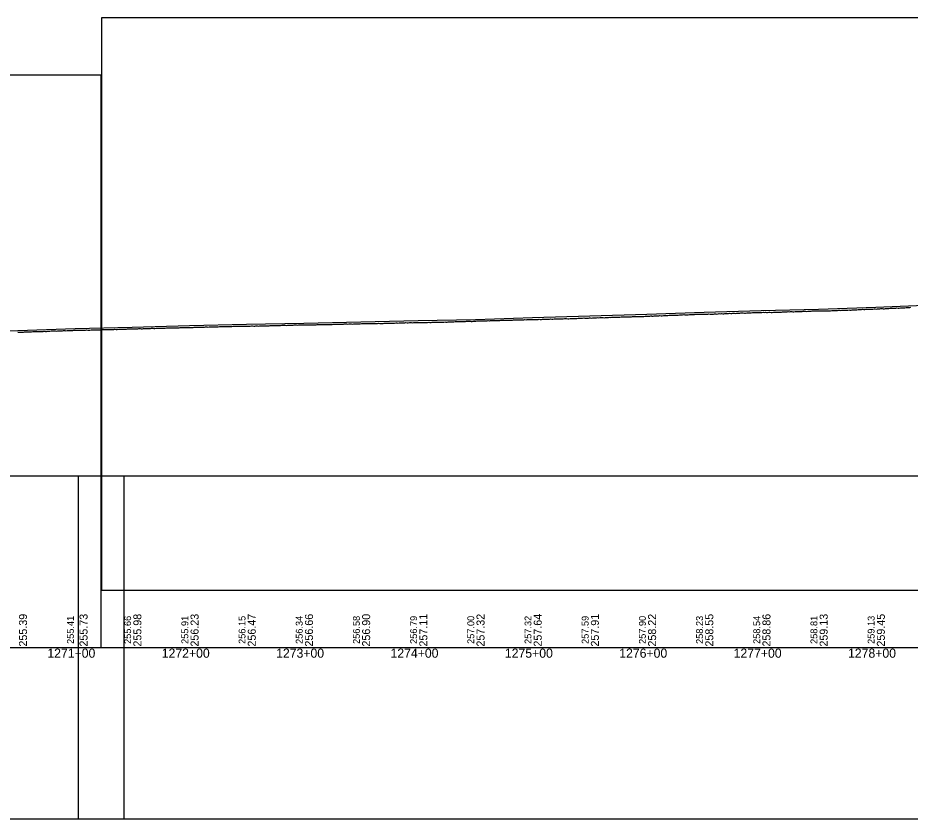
# Model space of a CAD drawing. Extents: x -3627 to 47473, y 2850 to 4350.
# Drawn here: x 14427 to 15207, y 2850 to 3550 of the extents above; entities that cross this region are included whole.
import ezdxf

# ---------------------------------------------------------------- set-up
doc = ezdxf.new("R2010")
doc.units = 0
for name, color, linetype in [('RD_DDB_Profile_EX', 7, 'Continuous'), ('RD_DDB_Profile_PR', 7, 'Continuous'), ('RD_DDB_StaTX', 7, 'Continuous'), ('RD_DDB_StripGrade', 7, 'Continuous'), ('RD_GPK_Profile_Cell', 7, 'Continuous'), ('RD_SHT_ShtClip', 7, 'Continuous')]:
    doc.layers.add(name, color=color, linetype=linetype)

msp = doc.modelspace()

# ---------------------------------------------------------------- linework, layer by layer
at = {"layer": 'RD_DDB_Profile_EX'}
for points in [[(15040.535467, 3291.620115), (15041.532076, 3291.55583), (15042.536778, 3291.601915), (15043.533383, 3291.53178), (15044.532911, 3291.473685), (15045.53718, 3291.79702), (15046.533783, 3291.75525), (15047.055087, 3291.729195), (15047.537993, 3291.70876), (15048.534898, 3291.79854), (15049.533692, 3291.897145), (15050.538461, 3291.854445), (15051.534928, 3291.80897), (15052.539074, 3291.9163), (15053.535543, 3291.881615), (15054.534341, 3291.83489), (15055.531853, 3291.970315), (15056.535996, 3292.016485), (15057.540017, 3292.162725), (15058.531012, 3292.105165), (15059.535031, 3292.190165), (15060.531356, 3292.23045), (15061.536415, 3292.30237), (15062.540443, 3292.116995), (15063.531429, 3292.1353), (15064.535456, 3292.270565), (15065.531766, 3292.289205), (15065.877865, 3292.27198), (15066.535716, 3292.24281), (15067.52716, 3292.239205), (15068.531475, 3292.335665), (15069.53538, 3292.48212), (15070.531541, 3292.5791), (15070.834701, 3292.5323), (15071.832752, 3292.53189), (15072.843867, 3292.481505), (15073.84248, 3292.48485), (15074.841012, 3292.580685), (15075.289254, 3292.625415), (15075.839032, 3292.67243), (15076.842887, 3292.67256), (15077.840872, 3292.714085), (15078.839485, 3292.771515), (15079.83748, 3292.67516), (15080.84131, 3292.80466), (15081.839829, 3292.666525), (15082.8449, 3292.619625), (15083.842884, 3292.86472), (15084.841555, 3292.909615), (15085.845284, 3292.682165), (15086.843214, 3292.731925), (15087.841727, 3292.90888), (15088.839665, 3292.999085), (15089.863008, 3292.926955), (15090.861194, 3292.921985), (15091.866519, 3292.97603), (15092.864692, 3292.88544), (15094.112032, 3292.945095), (15094.866936, 3292.940265), (15095.865008, 3293.045085), (15096.863672, 3293.145045), (15097.861749, 3293.260005), (15098.865197, 3293.18511), (15099.863867, 3293.229995), (15100.86923, 3293.339735), (15101.8673, 3293.25), (15102.865993, 3293.405215), (15103.869383, 3293.394825), (15104.867353, 3293.260425), (15105.865949, 3293.310475), (15106.863923, 3293.4), (15107.86724, 3293.444775), (15108.865837, 3293.54475), (15109.871054, 3293.562415), (15110.869668, 3293.601435), (15111.86764, 3293.472835), (15112.93481, 3293.45523), (15113.869462, 3293.667605), (15114.867335, 3293.66203), (15115.865207, 3293.62275), (15116.869049, 3293.571515), (15117.866922, 3293.721615), (15118.864794, 3293.88258), (15119.870539, 3293.810775), (15120.873732, 3293.754645), (15121.8716, 3294.10549), (15122.346199, 3294.1055), (15122.870076, 3294.1055), (15123.867848, 3294.094485), (15124.86628, 3294.088965), (15125.869366, 3294.044555), (15126.867139, 3294.05), (15127.865564, 3294.05), (15128.870552, 3294.05), (15129.873645, 3294.1), (15130.872073, 3294.1), (15131.869834, 3294.061005), (15132.867508, 3294.11101), (15133.86584, 3294.116495), (15134.868833, 3294.15), (15135.866507, 3294.18374)], [(15135.866507, 3294.18374), (15136.864829, 3294.1), (15137.869722, 3294.194505), (15138.873377, 3294.283795), (15139.871051, 3294.36757), (15140.868726, 3294.36755), (15141.168977, 3294.3525), (15141.866977, 3294.328425), (15142.864554, 3294.33923), (15143.867468, 3294.42883), (15144.865676, 3294.52363), (15145.863253, 3294.53947), (15146.805248, 3294.478535), (15147.809884, 3294.56749), (15148.80952, 3294.57771), (15149.809143, 3294.555725), (15150.814609, 3294.59422), (15151.848124, 3294.64405), (15152.845877, 3294.64405), (15153.846573, 3294.81331), (15154.85195, 3294.731415), (15155.853308, 3294.712695), (15156.858661, 3294.97429), (15157.85934, 3294.917045), (15158.852502, 3294.989895), (15159.991754, 3295.022785), (15160.859106, 3295.058595), (15161.864236, 3295.108165), (15162.864757, 3295.193), (15163.869855, 3295.221215), (15164.863727, 3295.220955), (15165.864274, 3295.385175), (15166.869354, 3295.33503), (15167.869885, 3295.31528), (15168.875757, 3295.415395), (15169.403143, 3295.46827), (15169.876208, 3295.47646), (15170.875115, 3295.526455), (15171.875512, 3295.57603), (15172.875909, 3295.567465), (15173.881623, 3295.559095), (15174.88202, 3295.6167), (15175.886842, 3295.74967), (15176.887224, 3295.707345), (15177.885716, 3295.6), (15178.886111, 3295.70865), (15179.886346, 3295.87366), (15180.890954, 3295.864665), (15181.891175, 3296.028265), (15182.896717, 3295.99598), (15183.889815, 3295.940935), (15184.894396, 3295.95), (15185.894627, 3296.094495), (15186.895853, 3296.1719), (15187.900401, 3296.24058), (15188.225921, 3296.20799), (15188.900517, 3296.140455), (15189.897832, 3296.37385), (15190.897901, 3296.351795), (15191.903276, 3296.36133), (15192.903345, 3296.47937), (15193.903414, 3296.529735), (15194.907732, 3296.449785), (15195.901888, 3296.55999), (15196.906206, 3296.460035), (15197.906237, 3296.47031), (15198.910363, 3296.66019), (15199.911349, 3296.67056), (15200.911256, 3296.76039), (15201.908454, 3296.8), (15202.908369, 3296.820935), (15203.914297, 3296.86052), (15204.915341, 3296.878775), (15205.919426, 3296.928705), (15207.048699, 3297.002285), (15207.912279, 3297.121585)], [(14753.655646, 3283.3), (14754.659692, 3283.34781), (14755.30203, 3283.31564), (14755.655629, 3283.302085), (14756.659588, 3283.2938), (14757.657479, 3283.430715), (14758.653684, 3283.49593), (14759.657325, 3283.402015), (14760.653781, 3283.5481), (14761.657498, 3283.596225), (14762.661166, 3283.546265), (14763.65151, 3283.59445), (14764.713419, 3283.641595), (14765.651576, 3283.60171), (14766.65518, 3283.79664), (14767.658843, 3283.60165), (14768.649038, 3283.601625), (14769.652906, 3283.74522), (14770.648955, 3283.74707), (14771.611445, 3283.75), (14772.609229, 3283.701505), (14773.613071, 3283.75), (14774.124808, 3283.77565), (14774.610385, 3283.79693), (14775.614136, 3283.898505), (14776.604161, 3283.894185), (14777.607723, 3283.945755), (14778.611251, 3283.94863), (14779.608927, 3283.998575), (14780.6125, 3283.998615), (14781.610178, 3283.99856), (14782.613703, 3283.998605), (14783.603525, 3283.951355), (14784.607174, 3283.951305), (14785.610625, 3283.9525), (14786.608027, 3284.1), (14787.611684, 3283.95248), (14788.609246, 3283.95), (14789.612549, 3284.05246), (14790.602411, 3284.1), (14791.607833, 3284.2), (14792.611443, 3284.14892), (14792.947586, 3284.132055), (14793.608982, 3284.1), (14794.612297, 3284.15105), (14795.609663, 3284.19783), (14796.605251, 3284.149075), (14797.602624, 3284.153845), (14798.605952, 3284.299105), (14799.609532, 3284.25), (14800.606906, 3284.348265), (14801.610243, 3284.3), (14802.607584, 3284.25167), (14803.602986, 3284.351985), (14804.600246, 3284.5), (14805.603484, 3284.451215), (14806.606805, 3284.402115), (14807.604151, 3284.45055), (14808.607403, 3284.499525), (14809.596654, 3284.648805), (14810.599921, 3284.7), (14811.770364, 3284.70863), (14812.600439, 3284.749745), (14813.603603, 3284.749835), (14814.600747, 3284.700175), (14815.603945, 3284.75008), (14816.593133, 3284.84995), (14817.597652, 3284.79943), (14818.594652, 3284.799515), (14819.599167, 3284.898855), (14820.631067, 3284.949515), (14821.181753, 3284.97717), (14821.628093, 3284.999525), (14822.325322, 3284.930535), (14822.632199, 3284.89994), (14823.629233, 3284.85), (14824.628181, 3284.80023), (14825.633222, 3284.998695), (14826.630251, 3284.999675), (14827.635301, 3284.999575), (14828.63233, 3285.197895), (14829.637296, 3285.19689), (14830.634321, 3285.196385), (14831.639322, 3285.2012), (14832.630216, 3285.201375), (14833.635041, 3285.20077), (14834.632085, 3285.347725), (14835.636897, 3285.398315), (14836.641683, 3285.39722), (14837.638608, 3285.445435), (14838.643651, 3285.49801), (14839.634587, 3285.44892), (14840.004531, 3285.467295), (14840.639275, 3285.498845), (14841.636093, 3285.54887), (14842.640914, 3285.59639), (14843.637733, 3285.50353), (14844.642507, 3285.553735), (14845.639326, 3285.59878), (14846.63819, 3285.69722), (14847.635006, 3285.6)], [(14847.635006, 3285.6), (14848.639604, 3285.589965), (14849.644157, 3285.785), (14850.641292, 3285.79415), (14851.645768, 3285.79848), (14852.648598, 3285.801485), (14853.653555, 3285.85), (14854.64458, 3285.89679), (14855.649544, 3285.94667), (14856.646105, 3286.04349), (14857.651069, 3286.044935), (14858.827309, 3285.9606), (14859.652469, 3286.003405), (14860.656986, 3286.098255), (14861.648181, 3286.09461), (14862.652688, 3286.092635), (14863.649401, 3286.14641), (14864.653908, 3286.14448), (14865.650319, 3286.14283), (14866.654916, 3286.14078), (14867.651333, 3286.14282), (14868.238698, 3286.14247), (14868.650567, 3286.148065), (14869.646828, 3286.2), (14870.651484, 3286.38281), (14871.655814, 3286.3364), (14872.652401, 3286.396225), (14873.656735, 3286.444245), (14874.653318, 3286.49255), (14875.657656, 3286.598105), (14876.648739, 3286.598065), (14877.653069, 3286.6), (14878.101109, 3286.6), (14879.099012, 3286.6), (14880.102986, 3286.59797), (14881.100583, 3286.458575), (14882.104858, 3286.504335), (14883.102451, 3286.693155), (14884.099568, 3286.6), (14885.103213, 3286.6), (14886.10114, 3286.75), (14887.105056, 3286.702375), (14888.10296, 3286.79752), (14889.106821, 3286.80498), (14890.097629, 3286.715025), (14891.101487, 3286.844975), (14892.099421, 3286.884305), (14893.103263, 3286.926385), (14894.107497, 3286.831545), (14895.105035, 3286.847265), (14896.108858, 3286.93629), (14896.472864, 3286.973025), (14897.099711, 3287.019755), (14898.103495, 3287.078035), (14899.101415, 3287.08014), (14900.105185, 3287.08017), (14901.103115, 3287.144155), (14902.106483, 3287.085375), (14903.103637, 3287.038645), (14904.10113, 3287.132455), (14905.105325, 3287.223675), (14906.102807, 3287.284965), (14907.106964, 3287.28801), (14908.104415, 3287.15921), (14909.108573, 3287.15612), (14910.099005, 3287.387815), (14911.103161, 3287.337855), (14912.116252, 3287.41981), (14913.114011, 3287.37828), (14914.118137, 3287.384535), (14915.295642, 3287.411725), (14916.112686, 3287.490785), (14917.109899, 3287.584305), (14918.113955, 3287.578175), (14919.111644, 3287.527665), (14920.115699, 3287.577815), (14921.119354, 3287.771615), (14922.117444, 3287.814575), (14923.113831, 3287.771925), (14924.111928, 3287.774505), (14924.707031, 3287.74497), (14925.115549, 3287.731), (14926.113081, 3287.774265), (14927.11666, 3287.964905), (14928.114686, 3287.88377), (14929.111004, 3287.79373), (14930.114989, 3287.809305), (14931.112611, 3288.03102), (14932.116596, 3287.84374), (14933.114217, 3288.01277), (14934.11842, 3288.10314), (14935.115754, 3288.00642), (14936.111913, 3288.09385), (14937.109465, 3288.128115), (14938.113381, 3288.16609), (14939.110933, 3288.0906), (14940.114849, 3288.04382), (14941.118376, 3288.28169), (14942.109027, 3288.15), (14942.754614, 3288.196945), (14943.760798, 3288.3)], [(14943.760798, 3288.3), (14944.763345, 3288.387485), (14945.761478, 3288.290515), (14946.759258, 3288.440395), (14947.757403, 3288.53059), (14948.760475, 3288.493625), (14949.758618, 3288.53068), (14950.764283, 3288.57325), (14951.762442, 3288.619605), (14952.941198, 3288.61451), (14953.762969, 3288.586615), (14954.760595, 3288.683125), (14955.758605, 3288.733015), (14956.769362, 3288.736315), (14957.767374, 3288.786225), (14958.764998, 3288.83264), (14959.763019, 3288.875545), (14960.760646, 3288.92887), (14961.763936, 3288.89309), (14962.352587, 3288.86355), (14962.760917, 3288.843055), (14963.76661, 3288.892865), (14964.764085, 3288.98925), (14965.767242, 3289.035965), (14966.764716, 3289.0859), (14967.762593, 3289.096465), (14968.760069, 3289.08934), (14969.763218, 3289.089565), (14970.76851, 3289.13569), (14971.766391, 3289.13565), (14972.763117, 3289.228475), (14973.723063, 3289.092985), (14974.720315, 3289.082435), (14975.718047, 3289.4219), (14976.722096, 3289.482), (14977.719348, 3289.492785), (14978.723461, 3289.485865), (14979.721196, 3289.482335), (14980.718449, 3289.575225), (14981.175365, 3289.5523), (14981.715696, 3289.532305), (14982.719749, 3289.4259), (14983.723796, 3289.61832), (14984.721038, 3289.72188), (14985.718758, 3289.80795), (14986.722347, 3289.7261), (14987.719588, 3289.59318), (14988.71683, 3289.926165), (14989.721856, 3289.74652), (14990.725447, 3289.75), (14991.722678, 3289.973005), (14992.720367, 3290.01647), (14993.717596, 3289.96996), (14994.721197, 3290.0144), (14995.718428, 3289.974235), (14996.722937, 3290.140155), (14997.720169, 3290.136935), (14998.7174, 3290.273995), (14999.998143, 3290.26415), (15000.71914, 3290.237495), (15001.716358, 3290.1907), (15002.720865, 3290.29055), (15003.724483, 3290.343925), (15004.721705, 3290.34699), (15005.718927, 3290.47014), (15006.716553, 3290.4675), (15007.507182, 3290.473855), (15008.505499, 3290.522575), (15009.510221, 3290.728325), (15010.507741, 3290.58161), (15011.512017, 3290.62823), (15012.50946, 3290.628525), (15013.507726, 3290.52442), (15014.504771, 3290.715225), (15015.50903, 3290.95512), (15016.513693, 3290.874045), (15017.504744, 3290.740125), (15018.508981, 3290.779985), (15018.82092, 3290.87391), (15019.506418, 3291.060555), (15020.510599, 3291.010155), (15021.515286, 3291.00969), (15022.506294, 3291.009245), (15023.510898, 3291.0055), (15024.507892, 3291.11623), (15025.512058, 3291.20908), (15026.503512, 3291.15527), (15027.507672, 3291.15485), (15028.511806, 3291.178985), (15029.532627, 3291.139665), (15030.537045, 3291.28956), (15031.528361, 3291.33593), (15032.533359, 3291.15), (15033.537767, 3291.1), (15034.534503, 3291.14645), (15035.533932, 3291.24268), (15036.530665, 3291.331925), (15037.643698, 3291.514475), (15038.532289, 3291.231985), (15039.536572, 3291.292745), (15040.535467, 3291.620115)], [(14454.367128, 3276.416905), (14455.364059, 3276.41114), (14456.368165, 3276.451255), (14457.359051, 3276.544565), (14458.362235, 3276.523825), (14459.366342, 3276.47045), (14460.363272, 3276.477515), (14461.360888, 3276.436755), (14462.364996, 3276.62674), (14463.361448, 3276.661055), (14464.365555, 3276.61743), (14465.369206, 3276.45), (14466.360098, 3276.590145), (14467.364205, 3276.773625), (14468.367378, 3276.75038), (14469.364768, 3276.611235), (14470.361924, 3276.73999), (14471.36603, 3276.78326), (14472.363415, 3276.93038), (14473.367067, 3276.930275), (14474.364207, 3276.87971), (14475.361137, 3276.88014), (14476.365244, 3277.066785), (14477.36935, 3277.063335), (14478.359796, 3277.079895), (14479.36342, 3277.10302), (14480.367058, 3277.10952), (14481.364457, 3277.033525), (14482.368563, 3277.126855), (14483.359005, 3277.17008), (14484.363113, 3277.166645), (14485.366275, 3277.12992), (14486.363669, 3277.22712), (14487.361295, 3277.366305), (14488.364934, 3277.276285), (14489.362323, 3277.240075), (14490.365492, 3277.230075), (14491.363111, 3277.372625), (14492.360505, 3277.45988), (14493.364147, 3277.359665), (14494.368253, 3277.429765), (14495.364708, 3277.47365), (14496.362324, 3277.422835), (14497.423897, 3277.43976), (14498.419959, 3277.57332), (14499.42367, 3277.52662), (14500.423018, 3277.6), (14501.41872, 3277.68989), (14502.422426, 3277.77638), (14503.426726, 3277.67291), (14504.417842, 3277.679615), (14505.421181, 3277.64659), (14506.425481, 3277.69316), (14507.421544, 3277.789975), (14508.22008, 3277.74312), (14509.217004, 3277.696645), (14510.22064, 3277.703375), (14511.224743, 3277.839845), (14512.221679, 3277.980205), (14513.219282, 3277.889795), (14514.222911, 3277.882905), (14515.219847, 3277.926665), (14516.22395, 3278.069895), (14517.228054, 3278.12986), (14518.218015, 3277.989895), (14519.222118, 3277.972965), (14520.226222, 3278.159305), (14521.223158, 3278.17025), (14522.220286, 3278.17269), (14523.2177, 3278.27332), (14524.221805, 3278.32992), (14525.224961, 3278.259705), (14526.222378, 3278.31066), (14527.219978, 3278.326335), (14528.223597, 3278.28307), (14529.220546, 3278.33012), (14530.224649, 3278.433375), (14531.221765, 3278.38632), (14532.21918, 3278.389975), (14533.222817, 3278.533205), (14534.219753, 3278.486905), (14535.223856, 3278.44343), (14536.221458, 3278.443225), (14537.217921, 3278.490075), (14538.222024, 3278.59004), (14539.226128, 3278.683345), (14540.216554, 3278.679985), (14541.220192, 3278.629875), (14542.224296, 3278.62981), (14543.221232, 3278.69016), (14544.225335, 3278.776965), (14545.222464, 3278.8194), (14546.2194, 3278.64006), (14547.223503, 3278.69335), (14548.220451, 3278.880485), (14549.217568, 3278.87991), (14550.221671, 3278.8), (14551.219077, 3278.9836), (14552.222251, 3278.98025), (14553.226353, 3278.98018), (14554.21725, 3278.98674)], [(14554.21725, 3278.98674), (14555.221355, 3278.99002), (14556.224516, 3278.99666), (14557.22193, 3279.18371), (14558.240872, 3279.133225), (14559.244622, 3279.17976), (14560.241523, 3279.183535), (14561.245702, 3279.28678), (14562.241667, 3279.33065), (14563.239917, 3279.326705), (14564.244096, 3279.34666), (14565.240565, 3279.346735), (14566.244745, 3279.280335), (14567.242489, 3279.279755), (14568.23896, 3279.3434), (14569.243139, 3279.433435), (14570.246897, 3279.533345), (14571.243279, 3279.58378), (14572.241534, 3279.529915), (14573.238002, 3279.486905), (14574.242181, 3279.490145), (14575.246361, 3279.583515), (14576.506977, 3279.44678), (14577.511088, 3279.54354), (14578.501975, 3279.543515), (14579.505642, 3279.49674), (14580.502502, 3279.64048), (14581.506616, 3279.69363), (14582.503499, 3279.69689), (14583.507612, 3279.743755), (14584.504472, 3279.690895), (14585.501353, 3279.738165), (14586.505467, 3279.84109), (14587.502745, 3279.841335), (14588.506461, 3279.83547), (14589.50332, 3279.835915), (14590.507433, 3279.85), (14591.504312, 3279.95), (14592.508426, 3280.044475), (14593.504915, 3279.90268), (14594.509027, 3279.94731), (14595.506275, 3280.042175), (14596.510027, 3280.039495), (14597.506897, 3279.99239), (14598.511009, 3280.087255), (14599.507895, 3280.135185), (14600.498567, 3280.19752), (14601.502683, 3280.140025), (14602.499195, 3280.04759), (14603.50331, 3280.233055), (14604.500504, 3280.23365), (14605.504297, 3280.235885), (14606.501152, 3280.28869), (14607.505267, 3280.3409), (14608.502138, 3280.347805), (14609.506253, 3280.334565), (14610.503107, 3280.335195), (14611.506928, 3280.39787), (14612.504091, 3280.39591), (14613.50096, 3280.39804), (14614.505074, 3280.398025), (14615.501927, 3280.540585), (14616.50578, 3280.540505), (14617.502909, 3280.55), (14618.507023, 3280.52994), (14619.503637, 3280.536115), (14620.534144, 3280.591275), (14621.529914, 3280.65), (14622.528786, 3280.651765), (14623.524254, 3280.74498), (14624.528258, 3280.639905), (14625.524191, 3280.593635), (14626.519649, 3280.7485), (14627.523685, 3280.74547), (14628.519159, 3280.74433), (14629.523459, 3280.74571), (14630.518933, 3280.794645), (14631.522995, 3280.89191), (14632.518841, 3280.89497), (14633.522918, 3280.648735), (14634.518398, 3280.647645), (14635.522488, 3280.89288), (14636.518178, 3280.89341), (14637.522282, 3280.747785), (14638.517778, 3280.84593), (14639.513274, 3280.895365), (14640.517672, 3280.94438), (14641.513158, 3280.993225), (14642.500212, 3281.042275), (14642.976039, 3281.042235), (14643.974039, 3281.0422), (14644.978069, 3280.99409), (14645.974417, 3280.99463), (14646.97226, 3281.001005), (14647.97657, 3281.19594), (14648.980593, 3281.18975), (14649.978426, 3281.13867), (14650.974946, 3281.195815), (14651.972792, 3281.243075), (14652.976792, 3281.189525), (14653.98079, 3281.19061)], [(14653.98079, 3281.19061), (14654.978957, 3281.2436), (14655.975307, 3281.19404), (14656.979301, 3281.34279), (14657.977116, 3281.440845), (14658.981296, 3281.440765), (14659.979104, 3281.391455), (14660.975473, 3281.481275), (14661.979823, 3281.335185), (14662.977641, 3281.394195), (14663.981593, 3281.436865), (14664.985543, 3281.435315), (14665.975996, 3281.5352), (14666.979943, 3281.59107), (14667.977734, 3281.63727), (14668.981866, 3281.687225), (14669.986044, 3281.737135), (14670.976284, 3281.688685), (14671.98021, 3281.680505), (14672.984388, 3281.777095), (14673.982166, 3281.791315), (14674.992575, 3281.73017), (14675.991505, 3281.732435), (14676.995585, 3281.73406), (14677.999859, 3281.689305), (14678.998479, 3281.73682), (14679.994262, 3281.778335), (14680.998536, 3281.780015), (14681.997485, 3281.88464), (14683.001213, 3281.884545), (14684.000157, 3281.827615), (14684.996166, 3281.828505), (14686.000223, 3281.942125), (14686.998832, 3281.941725), (14688.003105, 3281.94376), (14689.007146, 3281.997905), (14689.997869, 3282.039465), (14691.00178, 3282.087315), (14692.000509, 3282.038895), (14693.004783, 3282.084375), (14694.008671, 3282.082085), (14694.999185, 3282.08647), (14696.003458, 3282.1932), (14697.007731, 3282.147725), (14698.006315, 3282.147625), (14699.010322, 3282.19761), (14700.001129, 3282.2476), (14701.005403, 3282.152415), (14702.008992, 3282.102425), (14703.007983, 3282.339895), (14704.012256, 3282.342385), (14705.008084, 3282.345075), (14706.006657, 3282.39744), (14707.010929, 3282.442285), (14708.009652, 3282.444645), (14709.005776, 3282.4974), (14710.009602, 3282.54479), (14711.008325, 3282.49729), (14712.012597, 3282.547275), (14712.64755, 3282.59472), (14713.644816, 3282.594525), (14714.648561, 3282.594495), (14715.64577, 3282.497325), (14716.649891, 3282.586575), (14717.646697, 3282.67919), (14718.650461, 3282.58691), (14719.648111, 3282.539125), (14720.645303, 3282.73944), (14721.648676, 3282.686745), (14722.64587, 3282.68971), (14723.649991, 3282.652585), (14724.647284, 3282.79462), (14725.64409, 3282.834365), (14726.648211, 3282.84215), (14727.645041, 3282.934745), (14728.649162, 3282.88723), (14729.652909, 3282.84744), (14730.643262, 3282.9), (14731.66056, 3282.93447), (14732.656933, 3282.887485), (14733.660793, 3282.98992), (14734.664971, 3283.039875), (14735.655724, 3282.994915), (14736.659175, 3282.99234), (14737.6559, 3283.090135), (14738.660034, 3283.092585), (14739.663468, 3282.99752), (14740.660193, 3283.095215), (14741.658296, 3283.1), (14742.662114, 3283.2425), (14743.658452, 3283.09759), (14744.662586, 3283.1), (14745.890641, 3283.1), (14746.657023, 3283.1), (14747.660692, 3283.19759), (14748.657304, 3283.243065), (14749.661057, 3283.29538), (14750.65765, 3283.343365), (14751.661352, 3283.345595), (14752.659056, 3283.347705), (14753.655646, 3283.3)], [(14427.283254, 3275.37313), (14428.28012, 3275.3912), (14429.28433, 3275.30441), (14430.281173, 3275.354335), (14431.282354, 3275.375), (14432.286563, 3275.40404), (14433.283374, 3275.65), (14434.279023, 3275.64598), (14435.283232, 3275.7), (14436.280017, 3275.742095), (14437.283589, 3275.78417), (14438.27989, 3275.79223), (14439.276648, 3275.79239), (14440.280244, 3275.95), (14441.276537, 3275.9), (14442.273267, 3275.946345), (14443.277479, 3276), (14444.273606, 3275.9), (14445.277382, 3275.95), (14446.274087, 3275.95704), (14447.366654, 3275.95), (14448.37031, 3276.14029), (14449.361191, 3276.140255), (14450.364846, 3276.22388), (14451.368952, 3276.08362), (14452.365867, 3276.08723), (14453.363022, 3276.41042), (14454.367128, 3276.416905)]]:
    msp.add_lwpolyline(points, dxfattribs=at)
at = {"layer": 'RD_DDB_Profile_PR'}
msp.add_lwpolyline([(14377.33, 3275.15), (14427.33, 3276.974), (14477.33, 3278.6635), (14527.33, 3279.9215), (14577.33, 3281.126), (14627.33, 3282.346), (14677.33, 3283.319), (14727.33, 3284.5055), (14777.33, 3285.5315), (14827.33, 3286.5995), (14877.33, 3288.1995), (14927.33, 3289.5475), (14977.33, 3291.0885), (15027.33, 3292.755), (15077.33, 3294.293), (15127.33, 3295.65), (15177.33, 3297.2595), (15227.33, 3299.374)], dxfattribs=at)
at = {"layer": 'RD_GPK_Profile_Cell'}
msp.add_line((1000, 3000), (46705.077602, 3000), dxfattribs=at)
at = {"layer": 'RD_SHT_ShtClip'}
for points in [[(14500.33, 3550), (14500.33, 3050), (15953.33, 3050), (15953.33, 3050), (15953.33, 3550), (15953.33, 3550)], [(14500.165, 3000), (14500.165, 3500), (14500.165, 3500), (13000.33, 3500), (13000.33, 3000)], [(12980.33, 3150), (14520, 3150), (14520, 2850), (12980.33, 2850)], [(14480.33, 3150), (15973.33, 3150), (15973.33, 2850), (14480.33, 2850)]]:
    msp.add_lwpolyline(points, close=True, dxfattribs=at)

# ---------------------------------------------------------------- texts
at = {"layer": 'RD_DDB_StaTX'}
for s, p in [('1271+00', (14453.125471, 2991)), ('1272+00', (14553.125471, 2991)), ('1273+00', (14653.125471, 2991)), ('1274+00', (14753.125471, 2991)), ('1275+00', (14853.125471, 2991)), ('1276+00', (14953.125471, 2991)), ('1277+00', (15053.125471, 2991)), ('1278+00', (15153.125471, 2991))]:
    msp.add_text(s, height=8, dxfattribs=at).set_placement(p)
at = {"layer": 'RD_DDB_StripGrade'}
for s, height, p in [('255.39', 7, (14435.33, 3000.75)), ('255.41', 6, (14476.33, 3003.073688)), ('255.73', 7, (14488.270716, 3000.75)), ('255.66', 6, (14526.33, 3003.073688)), ('255.98', 7, (14535.33, 3000.75)), ('255.91', 6, (14576.33, 3003.073688)), ('256.23', 7, (14585.33, 3000.75)), ('256.15', 6, (14626.33, 3003.073688)), ('256.47', 7, (14635.33, 3000.75)), ('256.34', 6, (14676.33, 3003.073688)), ('256.66', 7, (14685.33, 3000.75)), ('256.58', 6, (14726.33, 3003.073688)), ('256.90', 7, (14735.33, 3000.75)), ('256.79', 6, (14776.33, 3003.073688)), ('257.11', 7, (14785.33, 3000.75)), ('257.00', 6, (14826.33, 3003.073688)), ('257.32', 7, (14835.33, 3000.75)), ('257.32', 6, (14876.33, 3003.073688)), ('257.64', 7, (14885.33, 3000.75)), ('257.59', 6, (14926.33, 3003.073688)), ('257.91', 7, (14935.33, 3000.75)), ('257.90', 6, (14976.33, 3003.073688)), ('258.22', 7, (14985.33, 3000.75)), ('258.23', 6, (15026.33, 3003.073688)), ('258.55', 7, (15035.33, 3000.75)), ('258.54', 6, (15076.33, 3003.073688)), ('258.86', 7, (15085.33, 3000.75)), ('258.81', 6, (15126.33, 3003.073688)), ('259.13', 7, (15135.33, 3000.75)), ('259.13', 6, (15176.33, 3003.073688)), ('259.45', 7, (15185.33, 3000.75))]:
    msp.add_text(s, height=height, rotation=90, dxfattribs=at).set_placement(p)

doc.saveas('drawing.dxf')
